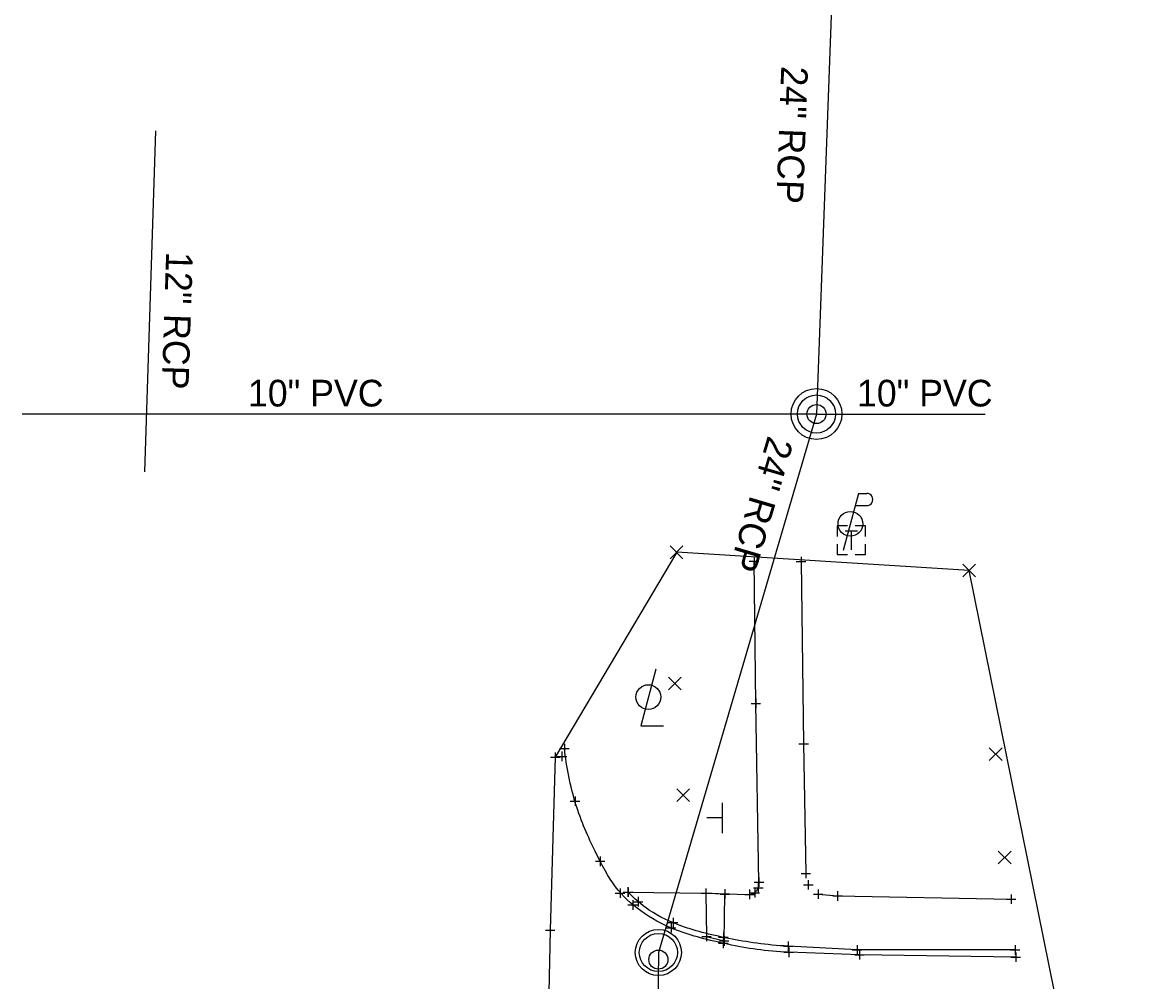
# Model space of a CAD drawing. Extents: x 1392719 to 1392850, y 437833 to 438309.
# Drawn here: x 1392719.2 to 1392836.5, y 438017.9 to 438118.6 of the extents above; entities that cross this region are included whole.
import ezdxf

# ---------------------------------------------------------------- set-up
doc = ezdxf.new("R2010")
doc.units = 0
for name, color, linetype in [('DR_X_Storm_Sewer', 7, 'Continuous'), ('PV_P_Curb_Ramp', 7, 'Continuous'), ('PV_X_Bikeway', 7, 'Continuous'), ('PV_X_Curb', 7, 'Continuous'), ('PV_X_EOP', 7, 'Continuous'), ('PV_X_Walk', 7, 'Continuous'), ('RD_P_Fence', 7, 'Continuous'), ('RD_X_Concrete_Pad', 7, 'Continuous'), ('RW_X_Fee_RW', 7, 'Continuous'), ('SC_Scratch6', 7, 'Continuous'), ('SH_Border', 7, 'Continuous'), ('SH_Data', 7, 'Continuous'), ('SV_X_Mon_Cells_Found', 7, 'Continuous'), ('SV_X_Terrain_Boundary', 7, 'Continuous'), ('TX_X_20', 7, 'Continuous')]:
    doc.layers.add(name, color=color, linetype=linetype)

msp = doc.modelspace()

# ---------------------------------------------------------------- linework, layer by layer
at = {"layer": 'DR_X_Storm_Sewer'}
for p, q in [((1392805.5, 438158.02), (1392802.55, 438077.47)), ((1392733.2, 438107.21), (1392732.05, 438071.39)), ((1392802.55, 438077.47), (1392719.21, 438077.47)), ((1392802.55, 438077.47), (1392785.96, 438020.94)), ((1392802.55, 438077.47), (1392820.24, 438077.47)), ((1392785.96, 438020.94), (1392785.48, 437980.73))]:
    msp.add_line(p, q, dxfattribs=at)
at = {"layer": 'PV_P_Curb_Ramp'}
for p, q in [((1392806.97, 438069.14), (1392805.36, 438063.14)), ((1392806.97, 438069.14), (1392807.82, 438069.14)), ((1392806.63, 438067.86), (1392807.82, 438067.86))]:
    msp.add_line(p, q, dxfattribs=at)
msp.add_circle((1392806.11, 438065.94), 1.3, dxfattribs=at)
msp.add_arc((1392807.83, 438068.5), 0.638, 268.8767, 91.1233, dxfattribs=at)
at = {"layer": 'PV_X_Bikeway'}
for p, q in [((1392805.56, 438065.22), (1392806.86, 438065.22)), ((1392806.21, 438063.22), (1392806.21, 438065.22)), ((1392806.21, 438064.22), (1392806.21, 438064.22))]:
    msp.add_line(p, q, dxfattribs=at)
for points in [[(1392805.81, 438065.72), (1392804.71, 438065.72), (1392804.71, 438064.62)], [(1392807.71, 438064.62), (1392807.71, 438065.72), (1392806.61, 438065.72)], [(1392804.71, 438063.82), (1392804.71, 438062.72), (1392805.81, 438062.72)], [(1392806.61, 438062.72), (1392807.71, 438062.72), (1392807.71, 438063.82)]]:
    msp.add_lwpolyline(points, dxfattribs=at)
at = {"layer": 'PV_X_Curb'}
for p, q in [((1392806.81, 438021.22), (1392799.58, 438021.6)), ((1392823.39, 438021.21), (1392806.81, 438021.22))]:
    msp.add_line(p, q, dxfattribs=at)
msp.add_open_spline([(1392799.58, 438021.6), (1392797.27, 438021.72), (1392793.21, 438022.34), (1392787.81, 438023.72), (1392784.48, 438025.58), (1392783.13, 438026.91), (1392782.8, 438027.27)], degree=3, dxfattribs=at)
at = {"layer": 'PV_X_EOP'}
for p, q in [((1392807.07, 438020.7), (1392799.64, 438020.96)), ((1392823.46, 438020.45), (1392807.07, 438020.7))]:
    msp.add_line(p, q, dxfattribs=at)
msp.add_lwpolyline([(1392775.84, 438041.53), (1392775.14, 438041.44), (1392774.6, 438023.27), (1392774.45, 438016.73), (1392774.27, 438006.86), (1392773.79, 437982.57), (1392773.61, 437973.7), (1392774.68, 437973.65), (1392774.4, 437957.61), (1392775.01, 437951.43), (1392777.98, 437945.86), (1392777.43, 437925.85), (1392776.73, 437901.16), (1392774.06, 437895.81), (1392773.6, 437888.63)], dxfattribs=at)
msp.add_open_spline([(1392799.64, 438020.96), (1392797.3, 438021.04), (1392793.16, 438021.74), (1392787.52, 438023.17), (1392783.97, 438025.26), (1392781.36, 438027.61), (1392779.36, 438031.37), (1392777.1, 438036.37), (1392776.31, 438040.46), (1392776.1, 438042.35)], degree=3, dxfattribs=at)
at = {"layer": 'PV_X_Walk'}
for p, q in [((1392796.18, 438047.09), (1392796, 438062.02)), ((1392800.93, 438061.98), (1392801.2, 438042.83)), ((1392796.51, 438028.32), (1392796.18, 438047.09)), ((1392801.2, 438042.83), (1392801.44, 438029.24)), ((1392782.76, 438027.29), (1392790.94, 438027.17)), ((1392790.94, 438027.17), (1392792.93, 438027.09)), ((1392792.93, 438027.09), (1392795.53, 438027.04)), ((1392802.73, 438027.07), (1392804.77, 438026.88)), ((1392804.77, 438026.88), (1392822.98, 438026.54))]:
    msp.add_line(p, q, dxfattribs=at)
msp.add_open_spline([(1392795.53, 438027.04), (1392795.74, 438027.04), (1392796.11, 438027.18), (1392796.49, 438027.71), (1392796.52, 438028.1), (1392796.51, 438028.32)], degree=3, dxfattribs=at)
at = {"layer": 'RD_P_Fence'}
for p, q in [((1392787.21, 438062.28), (1392788.54, 438063.62)), ((1392787.21, 438063.62), (1392788.54, 438062.28)), ((1392817.91, 438060.37), (1392819.24, 438061.71)), ((1392817.91, 438061.71), (1392819.24, 438060.37)), ((1392787.03, 438048.52), (1392788.36, 438049.86)), ((1392787.03, 438049.86), (1392788.36, 438048.52)), ((1392820.68, 438041.09), (1392822.02, 438042.42)), ((1392820.68, 438042.42), (1392822.02, 438041.09)), ((1392787.91, 438036.78), (1392789.24, 438038.12)), ((1392787.91, 438038.12), (1392789.24, 438036.78)), ((1392821.63, 438030.26), (1392822.97, 438031.59)), ((1392821.63, 438031.59), (1392822.97, 438030.26))]:
    msp.add_line(p, q, dxfattribs=at)
at = {"layer": 'RD_X_Concrete_Pad'}
msp.add_lwpolyline([(1392790.94, 438027.16), (1392791.01, 438022.62), (1392792.87, 438022.15), (1392792.94, 438027.06)], close=True, dxfattribs=at)
at = {"layer": 'RW_X_Fee_RW'}
for centre, radius in [((1392802.55, 438077.47), 2.67), ((1392802.55, 438077.47), 2), ((1392802.55, 438077.47), 1), ((1392785.96, 438020.94), 2.42), ((1392785.96, 438020.94), 2), ((1392785.96, 438020.19), 1)]:
    msp.add_circle(centre, radius, dxfattribs=at)
at = {"layer": 'SC_Scratch6'}
for p, q in [((1392795.5, 438062.02), (1392796.5, 438062.02)), ((1392796, 438062.52), (1392796, 438061.52)), ((1392796, 438062.02), (1392796, 438062.02)), ((1392800.43, 438061.98), (1392801.43, 438061.98)), ((1392800.93, 438062.48), (1392800.93, 438061.48)), ((1392800.93, 438061.98), (1392800.93, 438061.98)), ((1392796.18, 438047.59), (1392796.18, 438046.59)), ((1392795.68, 438047.09), (1392796.68, 438047.09)), ((1392796.18, 438047.09), (1392796.18, 438047.09)), ((1392776.1, 438042.85), (1392776.1, 438041.85)), ((1392800.7, 438042.83), (1392801.7, 438042.83)), ((1392801.2, 438043.33), (1392801.2, 438042.33)), ((1392801.2, 438042.83), (1392801.2, 438042.83)), ((1392775.14, 438041.94), (1392775.14, 438040.94)), ((1392775.34, 438041.53), (1392776.34, 438041.53)), ((1392775.6, 438042.35), (1392776.6, 438042.35)), ((1392775.84, 438042.03), (1392775.84, 438041.03)), ((1392775.84, 438041.53), (1392775.84, 438041.53)), ((1392776.1, 438042.35), (1392776.1, 438042.35)), ((1392774.64, 438041.44), (1392775.64, 438041.44)), ((1392775.14, 438041.44), (1392775.14, 438041.44)), ((1392776.71, 438036.82), (1392777.71, 438036.82)), ((1392777.21, 438037.32), (1392777.21, 438036.32)), ((1392777.21, 438036.82), (1392777.21, 438036.82)), ((1392779.85, 438031.02), (1392779.85, 438030.02)), ((1392779.35, 438030.52), (1392780.35, 438030.52)), ((1392779.85, 438030.52), (1392779.85, 438030.52)), ((1392796.51, 438028.82), (1392796.51, 438027.82)), ((1392800.94, 438029.24), (1392801.94, 438029.24)), ((1392801.44, 438029.74), (1392801.44, 438028.74)), ((1392801.44, 438029.24), (1392801.44, 438029.24)), ((1392781.94, 438027.67), (1392781.94, 438026.67)), ((1392782.76, 438027.79), (1392782.76, 438026.79)), ((1392782.8, 438027.77), (1392782.8, 438026.77)), ((1392790.94, 438027.67), (1392790.94, 438026.67)), ((1392790.94, 438027.66), (1392790.94, 438026.66)), ((1392792.93, 438027.59), (1392792.93, 438026.59)), ((1392792.94, 438027.56), (1392792.94, 438026.56)), ((1392795.53, 438027.54), (1392795.53, 438026.54)), ((1392795.94, 438027.72), (1392796.94, 438027.72)), ((1392796.01, 438028.32), (1392797.01, 438028.32)), ((1392796.07, 438027.72), (1392796.07, 438026.72)), ((1392796.44, 438028.22), (1392796.44, 438027.22)), ((1392796.44, 438027.72), (1392796.44, 438027.72)), ((1392796.51, 438028.32), (1392796.51, 438028.32)), ((1392801.19, 438028.04), (1392802.19, 438028.04)), ((1392801.69, 438028.54), (1392801.69, 438027.54)), ((1392801.69, 438028.04), (1392801.69, 438028.04)), ((1392802.73, 438027.57), (1392802.73, 438026.57)), ((1392781.44, 438027.17), (1392782.44, 438027.17)), ((1392781.94, 438027.17), (1392781.94, 438027.17)), ((1392782.26, 438027.29), (1392783.26, 438027.29)), ((1392782.3, 438027.27), (1392783.3, 438027.27)), ((1392782.76, 438027.29), (1392782.76, 438027.29)), ((1392782.8, 438027.27), (1392782.8, 438027.27)), ((1392783.27, 438026.43), (1392783.27, 438025.43)), ((1392783.33, 438026.27), (1392784.33, 438026.27)), ((1392783.83, 438026.77), (1392783.83, 438025.77)), ((1392783.83, 438026.27), (1392783.83, 438026.27)), ((1392790.44, 438027.17), (1392791.44, 438027.17)), ((1392790.44, 438027.16), (1392791.44, 438027.16)), ((1392790.94, 438027.17), (1392790.94, 438027.17)), ((1392790.94, 438027.16), (1392790.94, 438027.16)), ((1392792.43, 438027.09), (1392793.43, 438027.09)), ((1392792.44, 438027.06), (1392793.44, 438027.06)), ((1392792.93, 438027.09), (1392792.93, 438027.09)), ((1392792.94, 438027.06), (1392792.94, 438027.06)), ((1392795.03, 438027.04), (1392796.03, 438027.04)), ((1392795.53, 438027.04), (1392795.53, 438027.04)), ((1392795.57, 438027.22), (1392796.57, 438027.22)), ((1392796.07, 438027.22), (1392796.07, 438027.22)), ((1392802.23, 438027.07), (1392803.23, 438027.07)), ((1392802.73, 438027.07), (1392802.73, 438027.07)), ((1392804.27, 438026.88), (1392805.27, 438026.88)), ((1392804.77, 438027.38), (1392804.77, 438026.38)), ((1392804.77, 438026.88), (1392804.77, 438026.88)), ((1392822.48, 438026.54), (1392823.48, 438026.54)), ((1392822.98, 438027.04), (1392822.98, 438026.04)), ((1392822.98, 438026.54), (1392822.98, 438026.54)), ((1392782.77, 438025.93), (1392783.77, 438025.93)), ((1392783.27, 438025.93), (1392783.27, 438025.93)), ((1392787, 438024.08), (1392788, 438024.08)), ((1392787.3, 438024.03), (1392787.3, 438023.03)), ((1392787.5, 438024.58), (1392787.5, 438023.58)), ((1392787.5, 438024.08), (1392787.5, 438024.08)), ((1392774.1, 438023.27), (1392775.1, 438023.27)), ((1392774.6, 438023.77), (1392774.6, 438022.77)), ((1392774.6, 438023.27), (1392774.6, 438023.27)), ((1392786.8, 438023.53), (1392787.8, 438023.53)), ((1392787.3, 438023.53), (1392787.3, 438023.53)), ((1392791.01, 438023.12), (1392791.01, 438022.12)), ((1392792.78, 438023.04), (1392792.78, 438022.04)), ((1392790.51, 438022.62), (1392791.51, 438022.62)), ((1392791.01, 438022.62), (1392791.01, 438022.62)), ((1392792.27, 438021.91), (1392793.27, 438021.91)), ((1392792.28, 438022.54), (1392793.28, 438022.54)), ((1392792.37, 438022.15), (1392793.37, 438022.15)), ((1392792.77, 438022.41), (1392792.77, 438021.41)), ((1392792.77, 438021.91), (1392792.77, 438021.91)), ((1392792.78, 438022.54), (1392792.78, 438022.54)), ((1392792.87, 438022.65), (1392792.87, 438021.65)), ((1392792.87, 438022.15), (1392792.87, 438022.15)), ((1392799.08, 438021.6), (1392800.08, 438021.6)), ((1392799.58, 438022.1), (1392799.58, 438021.1)), ((1392799.58, 438021.6), (1392799.58, 438021.6)), ((1392806.81, 438021.72), (1392806.81, 438020.72)), ((1392823.39, 438021.71), (1392823.39, 438020.71)), ((1392799.14, 438020.96), (1392800.14, 438020.96)), ((1392799.64, 438021.46), (1392799.64, 438020.46)), ((1392799.64, 438020.96), (1392799.64, 438020.96)), ((1392806.31, 438021.22), (1392807.31, 438021.22)), ((1392806.57, 438020.7), (1392807.57, 438020.7)), ((1392806.81, 438021.22), (1392806.81, 438021.22)), ((1392807.07, 438021.2), (1392807.07, 438020.2)), ((1392807.07, 438020.7), (1392807.07, 438020.7)), ((1392822.89, 438021.21), (1392823.89, 438021.21)), ((1392822.96, 438020.45), (1392823.96, 438020.45)), ((1392823.39, 438021.21), (1392823.39, 438021.21)), ((1392823.46, 438020.95), (1392823.46, 438019.95)), ((1392823.46, 438020.45), (1392823.46, 438020.45))]:
    msp.add_line(p, q, dxfattribs=at)
at = {"layer": 'SH_Border'}
for p, q in [((1392792.65, 438036.66), (1392792.65, 438033.46)), ((1392792.65, 438035.06), (1392791.05, 438035.06))]:
    msp.add_line(p, q, dxfattribs=at)
at = {"layer": 'SH_Data'}
msp.add_lwpolyline([(1392785.7, 438050.7), (1392784.12, 438044.72), (1392786.48, 438044.72)], dxfattribs=at)
msp.add_circle((1392784.91, 438047.75), 1.3, dxfattribs=at)
at = {"layer": 'SV_X_Mon_Cells_Found'}
for p, q in [((1392800.55, 438077.47), (1392800.55, 438077.47)), ((1392802.55, 438077.47), (1392802.55, 438077.47)), ((1392802.55, 438077.47), (1392802.55, 438077.47)), ((1392802.55, 438077.47), (1392802.55, 438077.47)), ((1392804.55, 438077.47), (1392804.55, 438077.47)), ((1392785.96, 438022.94), (1392785.96, 438022.94)), ((1392785.96, 438020.94), (1392785.96, 438020.94)), ((1392785.96, 438020.94), (1392785.96, 438020.94)), ((1392785.96, 438020.19), (1392785.96, 438020.19)), ((1392785.96, 438018.94), (1392785.96, 438018.94))]:
    msp.add_line(p, q, dxfattribs=at)
for centre in [(1392802.55, 438077.47), (1392785.96, 438020.94)]:
    msp.add_circle(centre, 2, dxfattribs=at)
at = {"layer": 'SV_X_Terrain_Boundary'}
msp.add_lwpolyline([(1392773.6, 437888.63), (1392814.06, 437897.95), (1392835.82, 437960.81), (1392836.46, 437972.74), (1392818.58, 438061.04), (1392787.88, 438062.95), (1392775.14, 438041.44), (1392774.6, 438023.27), (1392774.45, 438016.73), (1392773.61, 437973.7)], close=True, dxfattribs=at)

# ---------------------------------------------------------------- texts
at = {"layer": 'TX_X_20'}
for s, rotation, p in [('24" RCP', 267.9078, (1392798.86, 438114.02)), ('12" RCP', 268.1668, (1392734.31, 438094.53)), ('24" RCP', 253.6438, (1392797.47, 438075.28))]:
    msp.add_text(s, height=2.8, rotation=rotation, dxfattribs=at).set_placement(p)
for p in [(1392742.89, 438078.26), (1392806.8, 438078.26)]:
    msp.add_text('10" PVC', height=2.8, dxfattribs=at).set_placement(p)

doc.saveas('drawing.dxf')
